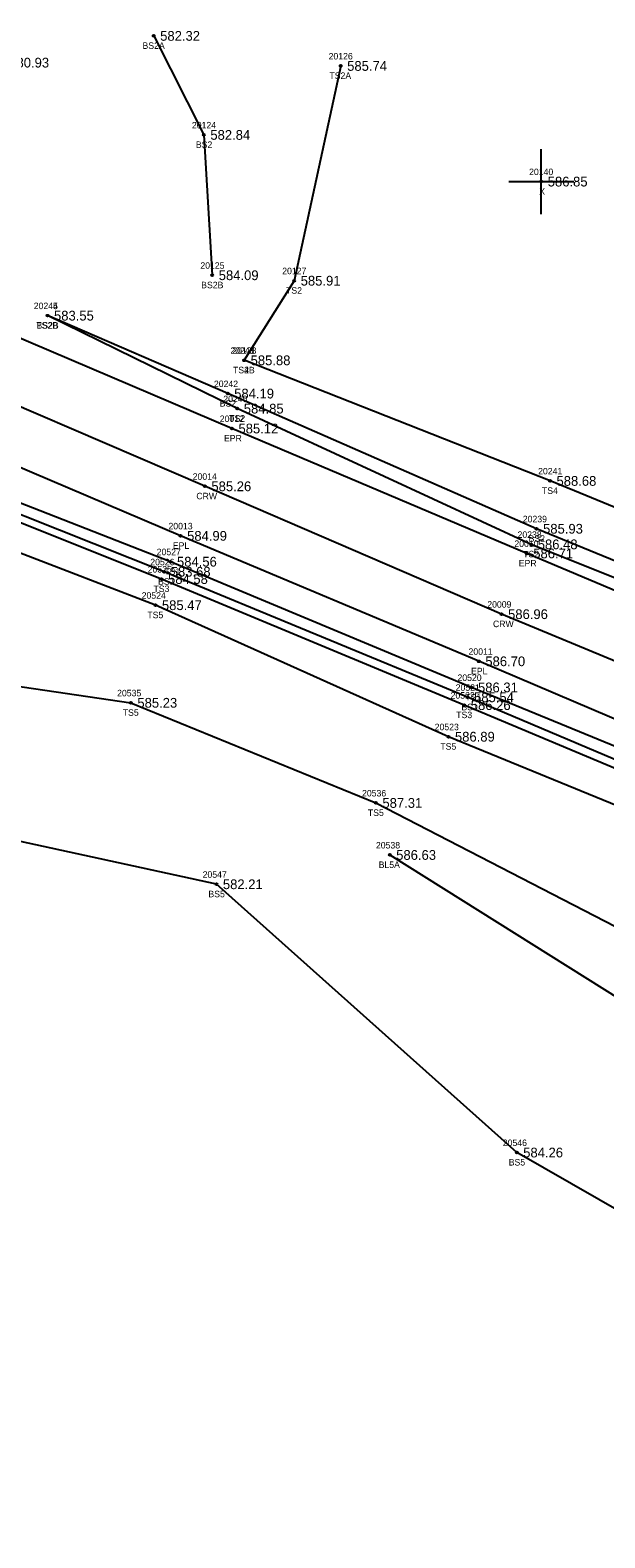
# Model space of a CAD drawing. Extents: x 1664837 to 1666270, y 987403 to 988245.
# Drawn here: x 1665947.9 to 1666036.4, y 987404.8 to 987637 of the extents above; entities that cross this region are included whole.
import ezdxf

# ---------------------------------------------------------------- set-up
doc = ezdxf.new("R2010")
doc.units = 0
for name, color, linetype in [('RD_DTM_BkLn1', 7, 'Continuous'), ('RD_DTM_BkLn2', 7, 'Continuous'), ('RD_DTM_BkLn_txCode', 7, 'Continuous'), ('RD_EX_Misc', 7, 'Continuous'), ('RD_EX_Misc_txCode', 7, 'Continuous'), ('RD_EX_Road', 7, 'Continuous'), ('RD_EX_Road_txCode', 7, 'Continuous'), ('RD_EX_TX_Misc_ELEV', 7, 'Continuous'), ('RD_EX_TX_Road_ELEV', 7, 'Continuous'), ('RD_HC_Survey_ELEV', 7, 'Continuous'), ('RD_HC_Survey_txCode', 7, 'Continuous'), ('RD_SMD_Locator', 7, 'Continuous')]:
    doc.layers.add(name, color=color, linetype=linetype)

msp = doc.modelspace()

# ---------------------------------------------------------------- linework, layer by layer
at = {"layer": 'RD_DTM_BkLn1'}
for points in [[(1666158.65, 987488.74), (1666112.69, 987508.17), (1666066.71, 987527.94), (1666020.54, 987547.08), (1665974.85, 987566.77), (1665928.96, 987586.52), (1665882.66, 987605.79), (1665836.76, 987625.38), (1665790.86, 987644.81), (1665744.75, 987663.93), (1665698.8, 987683.39), (1665652.93, 987702.82), (1665606.7, 987721.88), (1665561.04, 987742.04), (1665527.67, 987755.89)], [(1666003.31, 987510), (1666047.27, 987482.46), (1666094.38, 987450.1)]]:
    msp.add_lwpolyline(points, dxfattribs=at)
at = {"layer": 'RD_DTM_BkLn2'}
for points in [[(1666152.82, 987476.83), (1666108.53, 987496.54), (1666062.68, 987516.61), (1666015.91, 987535.8), (1665969.55, 987555.16), (1665926.09, 987572.12), (1665875.73, 987592.3), (1665829.7, 987613.88), (1665783.86, 987631.56), (1665738.66, 987650.04), (1665693.22, 987670.26), (1665645.99, 987690.14), (1665601.24, 987708.82), (1665555.03, 987727.9), (1665522.94, 987740.22)], [(1666117.29, 987404.85), (1666064.63, 987440.28), (1666022.87, 987464.18), (1665976.62, 987505.49), (1665934.85, 987514.58), (1665901.43, 987514.29), (1665891.04, 987542.26), (1665910.76, 987561.83), (1665873.03, 987584.83), (1665826.13, 987605.22), (1665781.49, 987626.06), (1665735.29, 987642.75), (1665690.09, 987662.74), (1665646.61, 987681.64)], [(1665966.96, 987636.13), (1665974.69, 987620.88), (1665975.98, 987599.27)], [(1665995.76, 987631.5), (1665988.6, 987598.43), (1665980.89, 987586.17)], [(1666163.34, 987500.12), (1666118.05, 987520.08), (1666071.65, 987539.17), (1666025.11, 987557.83), (1665979.84, 987578.73), (1665950.61, 987593.05)], [(1666164.39, 987501.91), (1666118.73, 987521.86), (1666072.1, 987541.26), (1666025.93, 987560.23), (1665978.36, 987581.05), (1665950.61, 987593.05)], [(1666152.2, 987475.35), (1666107.72, 987494.78), (1666061.84, 987514.6), (1666015.3, 987534.28), (1665968.59, 987553.61), (1665925.46, 987570.75), (1665883.85, 987585.11)], [(1666152.71, 987474.36), (1666107.47, 987494.11), (1666061.41, 987513.49), (1666014.8, 987533.07), (1665968.17, 987552.49), (1665925.11, 987569.65), (1665883.85, 987585.11)], [(1666169.13, 987510.14), (1666121.6, 987528.65), (1666075.19, 987548.23), (1666028, 987567.6), (1665980.89, 987586.17)], [(1666150.69, 987471.63), (1666103.73, 987485.25), (1666058.87, 987509.16), (1666012.36, 987528.21), (1665967.23, 987548.46), (1665923.96, 987565.08), (1665912.9, 987557.68), (1665922.58, 987537.56), (1665935.15, 987537.59), (1665963.45, 987533.43), (1666001.19, 987518.01), (1666046.03, 987494.86), (1666073.68, 987482.38), (1666094.38, 987450.1), (1666143.23, 987423.22)]]:
    msp.add_lwpolyline(points, dxfattribs=at)
at = {"layer": 'RD_EX_Misc'}
for p, q in [((1666026.65, 987608.69), (1666026.65, 987618.69)), ((1666021.65, 987613.69), (1666031.65, 987613.69))]:
    msp.add_line(p, q, dxfattribs=at)
at = {"layer": 'RD_EX_Road'}
for points in [[(1666163.18, 987497.62), (1666116.6, 987517.39), (1666070.7, 987536.94), (1666024.42, 987556.43), (1665979.02, 987575.67), (1665932.35, 987595.55), (1665886.93, 987614.54), (1665839.87, 987634.25), (1665794.5, 987653.27), (1665748.81, 987672.51), (1665702.36, 987691.87), (1665656.42, 987711.45), (1665610.33, 987731.03), (1665564.85, 987750.93), (1665531.47, 987764.82)], [(1666156.67, 987480.61), (1666109.28, 987500.74), (1666063.55, 987520.04), (1666017.04, 987539.82), (1665971.11, 987559.14), (1665924.88, 987578.79), (1665879.5, 987597.89), (1665833.22, 987617.38), (1665786.91, 987636.81), (1665741.44, 987656.13), (1665695.81, 987675.2), (1665649.26, 987694.85), (1665603.56, 987714.71), (1665558.4, 987733.87), (1665524.71, 987748.93)]]:
    msp.add_lwpolyline(points, dxfattribs=at)
at = {"layer": 'RD_SMD_Locator'}
for centre in [(1665966.96, 987636.13), (1665995.76, 987631.5), (1665974.69, 987620.88), (1666026.65, 987613.69), (1665975.98, 987599.27), (1665988.6, 987598.43), (1665950.61, 987593.05), (1665950.61, 987593.05), (1665980.89, 987586.17), (1665980.89, 987586.17), (1665978.36, 987581.05), (1665979.84, 987578.73), (1665979.02, 987575.67), (1665974.85, 987566.77), (1666028, 987567.6), (1665971.11, 987559.14), (1666025.93, 987560.23), (1666024.42, 987556.43), (1666025.11, 987557.83), (1665969.55, 987555.16), (1665968.17, 987552.49), (1665968.59, 987553.61), (1665967.23, 987548.46), (1666020.54, 987547.08), (1666017.04, 987539.82), (1666015.91, 987535.8), (1665963.45, 987533.43), (1666014.8, 987533.07), (1666015.3, 987534.28), (1666012.36, 987528.21), (1666001.19, 987518.01), (1666003.31, 987510), (1665976.62, 987505.49), (1666022.87, 987464.18)]:
    msp.add_circle(centre, 0.15, dxfattribs=at)

# ---------------------------------------------------------------- texts
at = {"layer": 'RD_DTM_BkLn_txCode'}
for s, p in [('BS2A', (1665965.24, 987634.13)), ('20126', (1665993.9, 987632.5)), ('TS2A', (1665994.03, 987629.5)), ('20124', (1665972.85, 987621.88)), ('BS2', (1665973.46, 987618.88)), ('20125', (1665974.15, 987600.27)), ('20127', (1665986.76, 987599.43)), ('BS2B', (1665974.28, 987597.27)), ('TS2', (1665987.35, 987596.43)), ('20244', (1665948.49, 987594.05)), ('20245', (1665948.49, 987594.05)), ('TS2B', (1665948.89, 987591.05)), ('BS2B', (1665948.91, 987591.05)), ('20243', (1665978.78, 987587.17)), ('20128', (1665979.06, 987587.17)), ('TS2B', (1665979.18, 987584.17)), ('TS4B', (1665979.18, 987584.17)), ('20242', (1665976.24, 987582.05)), ('BS2', (1665977.13, 987579.05)), ('20240', (1665977.68, 987579.73)), ('TS2', (1665978.6, 987576.73)), ('20241', (1666026.17, 987568.6)), ('TS4', (1666026.76, 987565.6)), ('20239', (1666023.81, 987561.23)), ('20238', (1666023, 987558.83)), ('BS2', (1666024.7, 987558.23)), ('20527', (1665967.43, 987556.16)), ('TS2', (1666023.87, 987555.83)), ('20525', (1665966.05, 987553.49)), ('20526', (1665966.44, 987554.61)), ('TS1', (1665968.59, 987553.16)), ('BS1', (1665967.64, 987551.61)), ('20524', (1665965.11, 987549.46)), ('TS3', (1665966.93, 987550.49)), ('TS5', (1665965.99, 987546.46)), ('20520', (1666013.75, 987536.8)), ('20535', (1665961.33, 987534.43)), ('20521', (1666013.47, 987535.28)), ('20522', (1666012.69, 987534.07)), ('BS1', (1666014.36, 987532.28)), ('TS1', (1666014.95, 987533.8)), ('TS5', (1665962.2, 987531.43)), ('TS3', (1666013.56, 987531.07)), ('20523', (1666010.24, 987529.21)), ('TS5', (1666011.11, 987526.21)), ('20536', (1665999.05, 987519.01)), ('TS5', (1665999.95, 987516.01)), ('20538', (1666001.19, 987511)), ('20547', (1665974.5, 987506.49)), ('BL5A', (1666001.61, 987508)), ('BS5', (1665975.39, 987503.49)), ('20546', (1666020.73, 987465.18)), ('BS5', (1666021.64, 987462.18))]:
    msp.add_text(s, height=1, dxfattribs=at).set_placement(p)
at = {"layer": 'RD_EX_Misc_txCode'}
for s, p in [('20140', (1666024.78, 987614.69)), ('X', (1666026.34, 987611.69))]:
    msp.add_text(s, height=1, dxfattribs=at).set_placement(p)
at = {"layer": 'RD_EX_Road_txCode'}
for s, p in [('20012', (1665977.14, 987576.67)), ('EPR', (1665977.79, 987573.67)), ('20013', (1665969.24, 987560.14)), ('EPL', (1665969.91, 987557.14)), ('20010', (1666022.51, 987557.43)), ('EPR', (1666023.19, 987554.43)), ('20011', (1666015.45, 987540.82)), ('EPL', (1666015.84, 987537.82))]:
    msp.add_text(s, height=1, dxfattribs=at).set_placement(p)
at = {"layer": 'RD_EX_TX_Misc_ELEV'}
for s, p in [('582.32', (1665967.96, 987635.38)), ('580.93', (1665944.72, 987631.26)), ('585.74', (1665996.76, 987630.75)), ('582.84', (1665975.69, 987620.13)), ('586.85', (1666027.65, 987612.94)), ('584.09', (1665976.98, 987598.52)), ('585.91', (1665989.6, 987597.68)), ('583.55', (1665951.61, 987592.3)), ('583.55', (1665951.61, 987592.3)), ('585.88', (1665981.89, 987585.42)), ('585.88', (1665981.89, 987585.42)), ('584.19', (1665979.36, 987580.3)), ('584.85', (1665980.84, 987577.98)), ('588.68', (1666029, 987566.85)), ('585.93', (1666026.93, 987559.48)), ('586.48', (1666026.11, 987557.08)), ('583.68', (1665969.59, 987552.86)), ('584.56', (1665970.55, 987554.41)), ('584.58', (1665969.17, 987551.74)), ('585.47', (1665968.23, 987547.71)), ('586.31', (1666016.91, 987535.05)), ('585.23', (1665964.45, 987532.68)), ('586.26', (1666015.8, 987532.32)), ('585.54', (1666016.3, 987533.53)), ('586.89', (1666013.36, 987527.46)), ('587.31', (1666002.19, 987517.26)), ('586.63', (1666004.31, 987509.25)), ('582.21', (1665977.62, 987504.74)), ('584.26', (1666023.87, 987463.43))]:
    msp.add_text(s, height=1.5, dxfattribs=at).set_placement(p)
at = {"layer": 'RD_EX_TX_Road_ELEV'}
for s, p in [('585.12', (1665980.02, 987574.92)), ('584.99', (1665972.11, 987558.39)), ('586.71', (1666025.42, 987555.68)), ('586.70', (1666018.04, 987539.07))]:
    msp.add_text(s, height=1.5, dxfattribs=at).set_placement(p)
at = {"layer": 'RD_HC_Survey_ELEV'}
for s, p in [('585.26', (1665975.85, 987566.02)), ('586.96', (1666021.54, 987546.33))]:
    msp.add_text(s, height=1.5, dxfattribs=at).set_placement(p)
at = {"layer": 'RD_HC_Survey_txCode'}
for s, p in [('20014', (1665972.97, 987567.77)), ('CRW', (1665973.53, 987564.77)), ('20009', (1666018.34, 987548.08)), ('CRW', (1666019.22, 987545.08))]:
    msp.add_text(s, height=1, dxfattribs=at).set_placement(p)

doc.saveas('drawing.dxf')
